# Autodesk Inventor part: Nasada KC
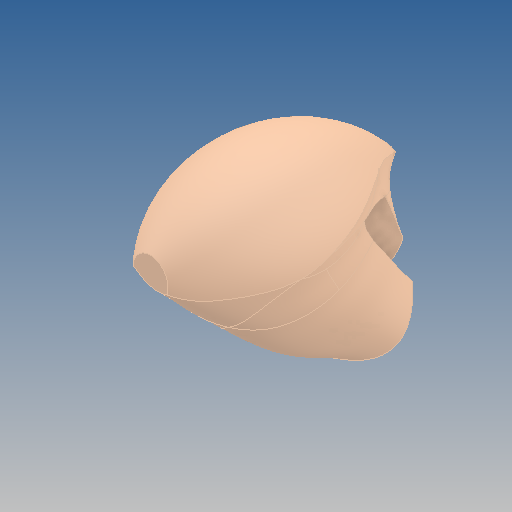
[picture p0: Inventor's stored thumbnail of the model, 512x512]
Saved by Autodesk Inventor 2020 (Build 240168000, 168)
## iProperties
Created: 2019-10
Part Number: Nasada KC
Material: GFRP
Document SubType Name: Modeling
Designer: yello
Density: 1.75 g/cm^3
Appearance: Default
Author: yello
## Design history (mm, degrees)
feature "Nasada KC"
body "Solid1"
